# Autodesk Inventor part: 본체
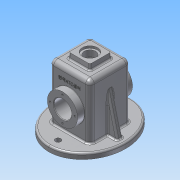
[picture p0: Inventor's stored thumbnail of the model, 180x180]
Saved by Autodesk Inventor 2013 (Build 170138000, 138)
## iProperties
Created: 2017-07
Part Number: 본체
Material: 알루미늄 6061
Document SubType Name: Modeling
Designer: Administrator
Density: 2.71 g/cm^3
Mass: 892.712 g
Surface Area: 987.353 cm^2
Volume: 329.414 cm^3
Author: Administrator
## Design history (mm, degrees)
sketch "스케치1"
  geometry: 4 further points; 1 other entity
  constraints: 1 coincident, 1 horizontal alignment, 1 vertical alignment, 4 other
  dimensions: "d1" = 65 distance of point (0, 0) point (0, 65); "d3" = 75 distance of point (75, 0) point (0, 0)
extrude "돌출1" new body sketch "스케치1" distance "d4" = 10; taper "d5" = 0 deg
sketch "스케치2"
  geometry: L1 (-37, -37)-(37, -37); L2 (37, -37)-(37, 37); L3 (37, 37)-(-37, 37); L4 (-37, 37)-(-37, -37); L5 (-37, -37)-(37, 37); L6 (37, -37)-(-37, 37); 1 further point; 1 other entity
  constraints: 12 end point, 2 midpoint, 2 parallel, 2 perpendicular, 1 horizontal, 1 other
  dimensions: "d6" = 74 distance of L2.end L3.end
extrude "돌출2" join sketch "스케치2" distance "d8" = 100; taper "d9" = 0 deg
sketch "스케치3"
  geometry: L1 (-20, 20)-(20, 20); L2 (20, 20)-(20, -20); L3 (20, -20)-(-20, -20); L4 (-20, -20)-(-20, 20); L5 (-20, 20)-(20, -20); L6 (20, 20)-(-20, -20); 1 further point
  constraints: 12 end point, 2 midpoint, 2 parallel, 2 perpendicular, 1 horizontal
  dimensions: "d10" = 40 distance of L1.start L1.end
extrude "돌출3" join sketch "스케치3" distance "d12" = 10; taper "d13" = -5 deg
sketch "스케치5"
  geometry: L1 (-32, 32)-(32, 32); L2 (32, 32)-(32, -32); L3 (32, -32)-(-32, -32); L4 (-32, -32)-(-32, 32); L5 (-32, 32)-(32, -32); L6 (32, 32)-(-32, -32); 1 further point; 1 other entity
  constraints: 12 end point, 2 midpoint, 2 parallel, 2 perpendicular, 1 horizontal, 1 other
  dimensions: "d20" = 64 distance of L1.start L1.end
extrude "돌출4" cut sketch "스케치5" distance "d22" = 105; taper "d23" = 0 deg
sketch "스케치6"
  geometry: L1 (-71.984, 55)-(71.132, 55); L2 (-75, 0)-(75, 0) reference; L3 (-50, 71)-(-25, 71); L4 (-25, 71)-(-25, 75.5); L5 (-25, 75.5)-(-32, 82.5); L6 (-32, 82.5)-(-50, 82.5); L7 (-50, 82.5)-(-50, 71); L8 (-32, 0)-(-32, 105) reference; L9 (-37, 10)-(-37, 110) reference; 1 further point
  constraints: 12 end point, 2 parallel, 1 horizontal, 1 perpendicular, 1 point on line, 1 vertical
  dimensions: "d24" = 55 distance between parallel lines of L2 L1; "d25" = 32 diameter of L3 L1; "d26" = 55 diameter of L6 L1; "d27" = 135 deg angle of L8 L5; "d28" = 7 distance from line of L8 L4.end; "d29" = 13 distance between parallel lines of L9 L7
revolve "회전1" sketch "스케치6" stored, may be unused: angle "d30" = 90 deg
sketch "스케치7"
  geometry: C1 r 16 at (0, 0) reference; 1 further point
extrude "돌출5" cut sketch "스케치7" distance "d31" = 25; taper "d32" = 0 deg
sketch "스케치8"
  geometry: C1 r 14 at (0, 0); 1 further point
  constraints: 1 centre point, 1 coincident
  dimensions: "d33" = 28 diameter of C1
extrude "돌출6" cut sketch "스케치8" distance "d35" = 4; taper "d36" = 0 deg
sketch "스케치9"
  geometry: C1 r 14 at (0, 0) reference; C2 r 10.5 at (0, 0)
  constraints: 1 centre point, 1 coincident
  dimensions: "d37" = 21 diameter of C2
extrude "돌출7" cut sketch "스케치9" stored distance "d39" = 4; taper "d40" = 0 deg
sketch "스케치10"
  geometry: L1 (-37, 10)-(-37, 110) reference; L2 (65, 10)-(-65, 10) reference; L3 (-37, 82.194)-(-55, 10); L4 (-65, 10)-(-65, -10.331); 1 further point
  constraints: 4 end point, 2 point on line, 1 perpendicular
  dimensions: "d41" = 10 distance of L3.end L2.end; "d42" = 14 deg angle of L3 L4; "d43" = 20.33099 distance of L2.end L4.end
feature "리브1" sketch "스케치10" dims "d44" = 1, "d45" = 10, "d46" = 0, "d47" = 0, "d48" = 1, "d49" = 1
fillet "모깎기1" dims "d50" = 3
sketch "스케치11"
  geometry: 1 further point
sketch "스케치12" dims "d51" = 45
  geometry: C1 r 27.5 at (0, 0) reference; C2 r 16 at (0, 0) reference; 3 further points
  constraints: 2 horizontal alignment, 1 coincident, 2 other
hole "구멍1" sketch "스케치12" at (-22.5, 0) diameter "d53" = 3.242; stored, may be unused: countersink angle "d57" = 90 deg, drill point angle "d59" = 118 deg; dims "d54" = 8, "d55" = 4, "d56" = 2, "d58" = 10
sketch "스케치13"
  geometry: C1 r 5 at (-58, 0); C2 r 5 at (58, 0); 1 further point; 1 other entity
  constraints: 2 centre point, 2 horizontal alignment, 1 equal radius, 1 other
  dimensions: "d63" = 58 distance of C1.centre point (0, 0); "d64" = 116 distance of C2.centre C1.centre; "d65" = 10 diameter of C1
extrude "돌출8" cut sketch "스케치13" stored distance "d66" = 4; taper "d67" = 0 deg
fillet "모깎기2" dims "d68" = 8
fillet "모깎기3" dims "d69" = 3
fillet "모깎기4" dims "d70" = 3
sketch "스케치14"
  geometry: L1 (-18, 48.125)-(-18, 9.875) reference; C1 r 27.5 at (47, 29) reference; 2 further points
  constraints: 1 horizontal alignment, 1 other
  dimensions: "d71" = 30 distance from line of point (12, 29) L1
feature "엠보싱1" sketch "스케치14" dims "d1" = 65, "d3" = 75, "d13" = -5 deg, "d72" = 0.5, "d73" = 0
fillet "모깎기5" dims "d74" = 0.5
fillet "모깎기6" dims "d75" = 0.5
chamfer "모따기1" distance "d76" = 1; stored, may be unused: second distance "d77" = 2, angle "d78" = 45 deg
fillet "모깎기7" dims "d79" = 3
fillet "모깎기8" dims "d80" = 3
sketch "스케치15" dims "d81" = 45
  geometry: C1 r 27.5 at (0, 0) reference; C2 r 17 at (0, 0) reference; 3 further points
  constraints: 2 horizontal alignment, 1 coincident, 2 other
hole "구멍2" sketch "스케치15" at (22.5, 0) diameter "d83" = 3.242; stored, may be unused: countersink angle "d87" = 90 deg, drill point angle "d89" = 118 deg; dims "d84" = 8, "d85" = 4, "d86" = 2, "d88" = 10
node "솔리드1"
mirror "대칭1"
mirror "대칭2"
pattern_circular "원형 패턴1" dims angle "d61" = 360 deg
pattern_circular "원형 패턴2" dims angle "d91" = 360 deg
